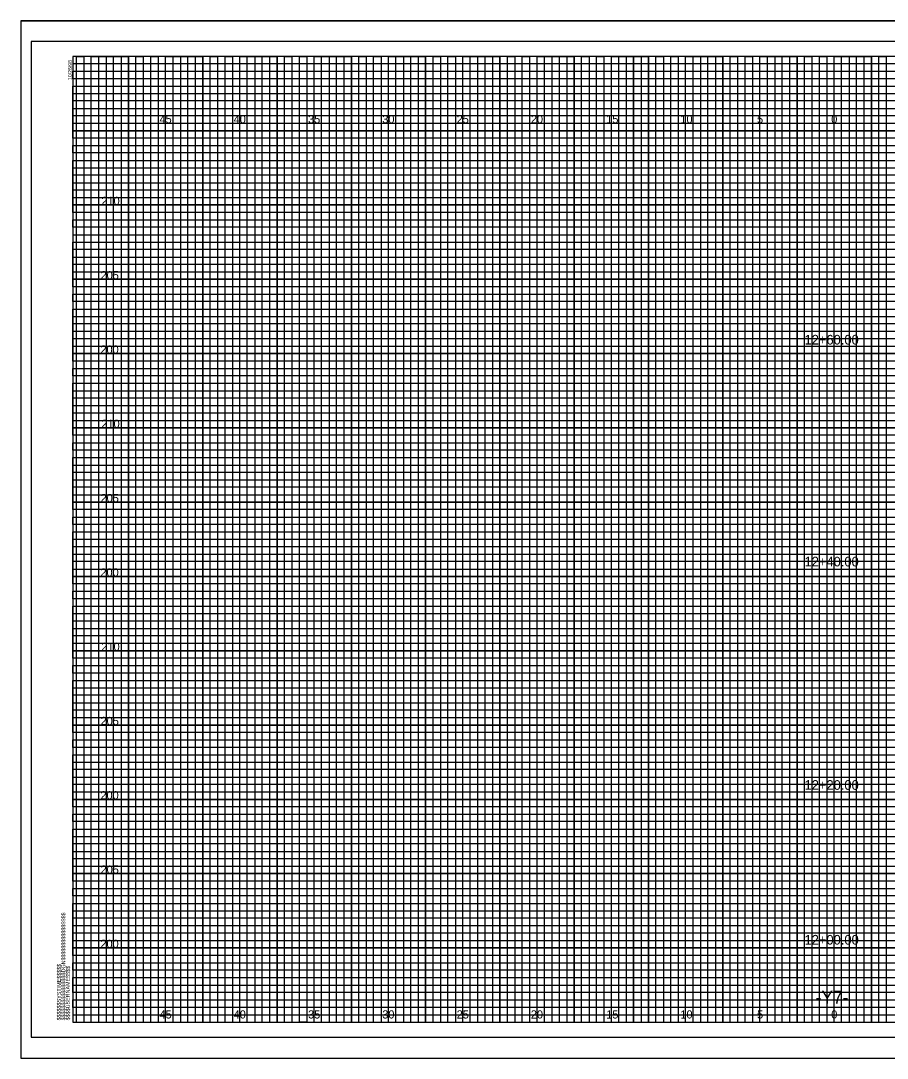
# Model space of a CAD drawing. Extents: x -4 to 103, y -2 to 351.
# Drawn here: x -3.5 to 54.8, y 139.2 to 209.1 of the extents above; entities that cross this region are included whole.
import ezdxf

# ---------------------------------------------------------------- set-up
doc = ezdxf.new("R2010")
doc.units = 0
for name, color, linetype in [('Exist XS Ground Line', 7, 'Continuous'), ('Old_Level_10', 7, 'Continuous'), ('Old_Level_16', 7, 'Continuous'), ('Old_Level_3', 7, 'Continuous'), ('Old_Level_4', 7, 'Continuous'), ('Old_Level_5', 7, 'Continuous'), ('Old_Level_6', 7, 'Continuous'), ('Old_Level_8', 7, 'Continuous'), ('Prop XS Finish Grade', 7, 'Continuous'), ('Prop XS SE Text', 7, 'Continuous'), ('Prop XS Subgrade Earthwork', 7, 'Continuous')]:
    doc.layers.add(name, color=color, linetype=linetype)

msp = doc.modelspace()

# ---------------------------------------------------------------- linework, layer by layer
at = {"layer": 'Old_Level_10'}
for p, q in [((1.25, 141.65), (1.25, 206.65)), ((3.75, 141.65), (3.75, 206.65)), ((6.25, 141.65), (6.25, 206.65)), ((8.75, 141.65), (8.75, 206.65)), ((11.25, 141.65), (11.25, 206.65)), ((13.75, 141.65), (13.75, 206.65)), ((16.25, 141.65), (16.25, 206.65)), ((18.75, 141.65), (18.75, 206.65)), ((21.25, 141.65), (21.25, 206.65)), ((23.75, 141.65), (23.75, 206.65)), ((26.25, 141.65), (26.25, 206.65)), ((28.75, 141.65), (28.75, 206.65)), ((31.25, 141.65), (31.25, 206.65)), ((33.75, 141.65), (33.75, 206.65)), ((36.25, 141.65), (36.25, 206.65)), ((38.75, 141.65), (38.75, 206.65)), ((41.25, 141.65), (41.25, 206.65)), ((43.75, 141.65), (43.75, 206.65)), ((46.25, 141.65), (46.25, 206.65)), ((48.75, 141.65), (48.75, 206.65)), ((51.25, 141.65), (51.25, 206.65)), ((53.75, 141.65), (53.75, 206.65)), ((0, 204.15), (74.25, 204.15)), ((0, 201.65), (102.5, 201.65)), ((0, 199.15), (102.5, 199.15)), ((0, 196.65), (102.5, 196.65)), ((0, 194.15), (102.5, 194.15)), ((0, 191.65), (102.5, 191.65)), ((0, 189.15), (102.5, 189.15)), ((0, 186.65), (102.5, 186.65)), ((0, 184.15), (102.5, 184.15)), ((0, 181.65), (102.5, 181.65)), ((0, 179.15), (102.5, 179.15)), ((0, 176.65), (102.5, 176.65)), ((0, 174.15), (102.5, 174.15)), ((0, 171.65), (102.5, 171.65)), ((0, 169.15), (102.5, 169.15)), ((0, 166.65), (102.5, 166.65)), ((0, 164.15), (102.5, 164.15)), ((0, 161.65), (102.5, 161.65)), ((0, 159.15), (102.5, 159.15)), ((0, 156.65), (102.5, 156.65)), ((0, 154.15), (102.5, 154.15)), ((0, 151.65), (102.5, 151.65)), ((0, 149.15), (102.5, 149.15)), ((0, 146.65), (102.5, 146.65)), ((0, 144.15), (102.5, 144.15))]:
    msp.add_line(p, q, dxfattribs=at)
at = {"layer": 'Old_Level_3'}
for p, q in [((-3.5, 209.05), (103.4, 209.05)), ((-3.5, 209.05), (-3.5, 139.225)), ((-3.5, 139.225), (102.1625, 139.225))]:
    msp.add_line(p, q, dxfattribs=at)
at = {"layer": 'Old_Level_4'}
for points in [[(0, 203.65), (0, 204.65), (74.25, 204.65), (74.25, 205.15), (0, 205.15), (0, 205.65), (74.25, 205.65), (74.25, 206.15), (0, 206.15)], [(0.25, 141.65), (0.25, 206.65), (0.75, 206.65), (0.75, 141.65), (1.75, 141.65), (1.75, 206.65), (2.25, 206.65), (2.25, 141.65), (2.75, 141.65), (2.75, 206.65), (3.25, 206.65), (3.25, 141.65), (4.25, 141.65), (4.25, 206.65), (4.75, 206.65), (4.75, 141.65), (5.25, 141.65), (5.25, 206.65), (5.75, 206.65), (5.75, 141.65), (6.75, 141.65), (6.75, 206.65), (7.25, 206.65), (7.25, 141.65), (7.75, 141.65), (7.75, 206.65), (8.25, 206.65), (8.25, 141.65), (9.25, 141.65), (9.25, 206.65), (9.75, 206.65), (9.75, 141.65), (10.25, 141.65), (10.25, 206.65), (10.75, 206.65), (10.75, 141.65), (11.75, 141.65), (11.75, 206.65), (12.25, 206.65), (12.25, 141.65), (12.75, 141.65), (12.75, 206.65), (13.25, 206.65), (13.25, 141.65), (14.25, 141.65), (14.25, 206.65), (14.75, 206.65), (14.75, 141.65), (15.75, 141.65), (15.25, 141.65), (15.25, 206.65), (15.75, 206.65), (15.75, 141.65), (16.75, 141.65), (16.75, 206.65), (17.25, 206.65), (17.25, 141.65), (17.75, 141.65), (17.75, 206.65), (18.25, 206.65), (18.25, 141.65), (19.25, 141.65), (19.25, 206.65), (19.75, 206.65), (19.75, 141.65), (20.25, 141.65), (20.25, 206.65), (20.75, 206.65), (20.75, 141.65), (21.75, 141.65), (21.75, 206.65), (22.25, 206.65), (22.25, 141.65), (22.75, 141.65), (22.75, 206.65), (23.25, 206.65), (23.25, 141.65), (24.25, 141.65), (24.25, 206.65), (24.75, 206.65), (24.75, 141.65), (25.25, 141.65), (25.25, 206.65), (25.75, 206.65), (25.75, 141.65), (26.75, 141.65), (26.75, 206.65), (27.25, 206.65), (27.25, 141.65), (27.75, 141.65), (27.75, 206.65), (28.25, 206.65), (28.25, 141.65), (29.25, 141.65), (29.25, 206.65), (29.75, 206.65), (29.75, 141.65), (30.25, 141.65), (30.25, 206.65), (30.75, 206.65), (30.75, 141.65)], [(30.75, 141.65), (31.75, 141.65), (31.75, 206.65), (32.25, 206.65), (32.25, 141.65), (32.75, 141.65), (32.75, 206.65), (33.25, 206.65), (33.25, 141.65), (34.25, 141.65), (34.25, 206.65), (34.75, 206.65), (34.75, 141.65), (35.25, 141.65), (35.25, 206.65), (35.75, 206.65), (35.75, 141.65), (36.75, 141.65), (36.75, 206.65), (37.25, 206.65), (37.25, 141.65), (37.75, 141.65), (37.75, 206.65), (37.75, 141.65)], [(38.25, 206.65), (38.25, 141.65), (39.25, 141.65), (39.25, 206.65), (39.75, 206.65), (39.75, 141.65), (40.25, 141.65), (40.25, 206.65), (40.75, 206.65), (40.75, 141.65), (41.75, 141.65), (41.75, 206.65), (42.25, 206.65), (42.25, 141.65), (42.75, 141.65), (42.75, 206.65), (43.25, 206.65), (43.25, 141.65), (43.75, 141.65), (44.25, 141.65), (44.25, 206.65), (44.75, 206.65), (44.75, 141.65), (45.25, 141.65), (45.25, 206.65), (45.75, 206.65), (45.75, 141.65), (46.75, 141.65), (46.75, 206.65), (47.25, 206.65), (47.25, 141.65), (47.75, 141.65), (47.75, 206.65), (48.25, 206.65), (48.25, 141.65), (49.25, 141.65), (49.25, 206.65), (49.75, 206.65), (49.75, 141.65), (50.25, 141.65), (50.25, 206.65), (50.75, 206.65), (50.75, 141.65), (51.75, 141.65), (51.75, 206.65), (52.25, 206.65), (52.25, 141.65), (52.75, 141.65), (52.75, 206.65), (53.25, 206.65), (53.25, 141.65), (54.25, 141.65), (54.25, 206.65), (54.75, 206.65), (54.75, 141.65), (55.25, 141.65)], [(102.5, 203.65), (0, 203.65)], [(102.5, 202.65), (0, 202.65), (0, 203.15), (102.5, 203.15)], [(102.5, 201.15), (0, 201.15), (0, 202.15), (102.5, 202.15)], [(102.5, 200.15), (0, 200.15), (0, 200.65), (102.5, 200.65)], [(102.5, 198.65), (0, 198.65), (0, 199.65), (102.5, 199.65)], [(102.5, 197.65), (0, 197.65), (0, 198.15), (102.5, 198.15)], [(102.5, 196.15), (0, 196.15), (0, 197.15), (102.5, 197.15)], [(102.5, 195.15), (0, 195.15), (0, 195.65), (102.5, 195.65)], [(0, 194.65), (102.5, 194.65)], [(102.5, 193.65), (0, 193.65)], [(102.5, 192.65), (0, 192.65), (0, 193.15), (102.5, 193.15)], [(102.5, 191.15), (0, 191.15), (0, 192.15), (102.5, 192.15)], [(102.5, 190.15), (0, 190.15), (0, 190.65), (102.5, 190.65)], [(102.5, 188.65), (0, 188.65), (0, 189.65), (102.5, 189.65)], [(102.5, 187.65), (0, 187.65), (0, 188.15), (102.5, 188.15)], [(102.5, 186.15), (0, 186.15), (0, 187.15), (102.5, 187.15)], [(102.5, 185.15), (0, 185.15), (0, 185.65), (102.5, 185.65)], [(102.5, 183.65), (0, 183.65), (0, 184.65), (102.5, 184.65)], [(102.5, 182.65), (0, 182.65), (0, 183.15), (102.5, 183.15)], [(102.5, 181.15), (0, 181.15), (0, 182.15), (102.5, 182.15)], [(102.5, 180.15), (0, 180.15), (0, 180.65), (102.5, 180.65)], [(102.5, 178.65), (0, 178.65), (0, 179.65), (102.5, 179.65)], [(102.5, 177.65), (0, 177.65), (0, 178.15), (102.5, 178.15)], [(102.5, 176.15), (0, 176.15), (0, 177.15), (102.5, 177.15)], [(102.5, 175.15), (0, 175.15), (0, 175.65), (102.5, 175.65)], [(102.5, 173.65), (0, 173.65), (0, 174.65), (102.5, 174.65)], [(102.5, 172.65), (0, 172.65), (0, 173.15)], [(0, 173.15), (102.5, 173.15)], [(102.5, 171.15), (0, 171.15), (0, 172.15), (102.5, 172.15)], [(102.5, 170.15), (0, 170.15), (0, 170.65), (102.5, 170.65)], [(102.5, 168.65), (0, 168.65), (0, 169.65), (102.5, 169.65)], [(102.5, 167.65), (0, 167.65), (0, 168.15), (102.5, 168.15)], [(102.5, 166.15), (0, 166.15), (0, 167.15), (102.5, 167.15)], [(102.5, 165.15), (0, 165.15), (0, 165.65), (102.5, 165.65)], [(102.5, 163.65), (0, 163.65), (0, 164.65), (102.5, 164.65)], [(102.5, 162.65), (0, 162.65), (0, 163.15), (102.5, 163.15)], [(102.5, 161.15), (0, 161.15), (0, 162.15), (102.5, 162.15)], [(102.5, 160.15), (0, 160.15), (0, 160.65), (102.5, 160.65)], [(102.5, 158.65), (0, 158.65), (0, 159.65), (102.5, 159.65)], [(102.5, 157.65), (0, 157.65), (0, 158.15), (102.5, 158.15)], [(102.5, 156.15), (0, 156.15), (0, 157.15), (102.5, 157.15)], [(102.5, 155.15), (0, 155.15), (0, 155.65), (102.5, 155.65)], [(102.5, 153.65), (0, 153.65), (0, 154.65), (102.5, 154.65)], [(102.5, 152.65), (0, 152.65), (0, 153.15), (102.5, 153.15)], [(102.5, 151.15), (0, 151.15), (0, 152.15), (102.5, 152.15)], [(102.5, 150.15), (0, 150.15), (0, 150.65), (102.5, 150.65)], [(102.5, 148.65), (0, 148.65), (0, 149.65), (102.5, 149.65)], [(102.5, 147.65), (0, 147.65), (0, 148.15), (102.5, 148.15)], [(102.5, 146.15), (0, 146.15), (0, 147.15), (102.5, 147.15)], [(102.5, 145.15), (0, 145.15), (0, 145.65), (102.5, 145.65)], [(102.5, 143.65), (0, 143.65), (0, 144.65), (102.5, 144.65)], [(102.5, 142.65), (0, 142.65), (0, 143.15), (102.5, 143.15)], [(0, 142.15), (102.5, 142.15)]]:
    msp.add_lwpolyline(points, dxfattribs=at)
at = {"layer": 'Old_Level_5'}
msp.add_lwpolyline([(103.4, 209.05), (-3.5, 209.05), (-3.5, 139.225), (103.4, 139.225)], close=True, dxfattribs=at)
at = {"layer": 'Old_Level_6'}
for p, q in [((0, 141.65), (0, 141.65)), ((0, 141.65), (0, 141.65)), ((-3.5, 139.225), (103.4, 139.225))]:
    msp.add_line(p, q, dxfattribs=at)
msp.add_lwpolyline([(102.5, 206.65), (0, 206.65), (0, 141.65), (102.5, 141.65)], close=True, dxfattribs=at)
at = {"layer": 'Old_Level_8'}
for points in [[(1.25, 141.65), (1.25, 206.65), (3.75, 206.65), (3.75, 141.65), (6.25, 141.65), (6.25, 206.65), (8.75, 206.65), (8.75, 141.65), (11.25, 141.65), (11.25, 206.65), (13.75, 206.65), (13.75, 141.65), (16.25, 141.65), (16.25, 206.65), (18.75, 206.65), (18.75, 141.65), (21.25, 141.65), (21.25, 206.65), (23.75, 206.65), (23.75, 141.65), (26.25, 141.65), (26.25, 206.65), (28.75, 206.65), (28.75, 141.65), (31.25, 141.65), (31.25, 206.65), (33.75, 206.65), (33.75, 141.65), (36.25, 141.65), (36.25, 206.65), (38.75, 206.65), (38.75, 141.65), (41.25, 141.65), (41.25, 206.65), (43.75, 206.65), (43.75, 141.65), (46.25, 141.65), (46.25, 206.65), (48.75, 206.65), (48.75, 141.65), (51.25, 141.65), (51.25, 206.65), (53.75, 206.65), (53.75, 141.65)], [(102.5, 201.65), (0, 201.65), (0, 204.15), (74.25, 204.15)], [(102.5, 196.65), (0, 196.65), (0, 199.15), (102.5, 199.15)], [(102.5, 191.65), (0, 191.65), (0, 194.15), (102.5, 194.15)], [(102.5, 186.65), (0, 186.65), (0, 189.15), (102.5, 189.15)], [(102.5, 181.65), (0, 181.65), (0, 184.15), (102.5, 184.15)], [(102.5, 176.65), (0, 176.65), (0, 179.15), (102.5, 179.15)], [(102.5, 171.65), (0, 171.65), (0, 174.15), (102.5, 174.15)], [(102.5, 166.65), (0, 166.65), (0, 169.15), (102.5, 169.15)], [(102.5, 161.65), (0, 161.65), (0, 164.15), (102.5, 164.15)], [(102.5, 156.65), (0, 156.65), (0, 159.15), (102.5, 159.15)], [(102.5, 151.65), (0, 151.65), (0, 154.15), (102.5, 154.15)], [(102.5, 146.65), (0, 146.65), (0, 149.15), (102.5, 149.15)], [(0, 144.15), (102.5, 144.15)]]:
    msp.add_lwpolyline(points, dxfattribs=at)
at = {"layer": 'Prop XS SE Text'}
msp.add_lwpolyline([(103, 207.65), (-2.8, 207.65), (-2.8, 140.65), (103, 140.65)], close=True, dxfattribs=at)

# ---------------------------------------------------------------- texts
at = {"layer": 'Exist XS Ground Line'}
msp.add_text('-Y7-', height=0.875, dxfattribs=at).set_placement((49.9985, 142.9))
at = {"layer": 'Old_Level_16'}
for s, p in [('45', (5.8399, 202.15)), ('40', (10.8313, 202.15)), ('35', (15.8399, 202.15)), ('30', (20.8313, 202.15)), ('25', (25.8399, 202.15)), ('20', (30.8313, 202.15)), ('15', (35.9058, 202.15)), ('10', (40.8971, 202.15)), ('5', (46.0574, 202.15)), ('0', (51.0488, 202.15)), ('0', (51.0488, 202.15)), ('45', (5.8399, 141.9)), ('40', (10.8313, 141.9)), ('35', (15.8399, 141.9)), ('30', (20.8313, 141.9)), ('25', (25.8399, 141.9)), ('20', (30.8313, 141.9)), ('15', (35.9058, 141.9)), ('10', (40.8971, 141.9)), ('5', (46.0574, 141.9)), ('0', (51.0488, 141.9)), ('0', (51.0488, 141.9))]:
    msp.add_text(s, height=0.55, dxfattribs=at).set_placement(p)
at = {"layer": 'Old_Level_6'}
for s, height, p in [('10/26/98', 0.25, (-0.0625, 205.0595)), ('$$$$$$$$$$$$$$$$DGN$$$$$$$$$$$$$$$$', 0.2625, (-0.5, 141.775)), ('$$$$$$SYSTIME$$$$$', 0.2625, (-0.7973, 141.7747)), ('$$$$USERNAME$$$$', 0.2625, (-0.2, 141.775))]:
    msp.add_text(s, height=height, rotation=90, dxfattribs=at).set_placement(p)
at = {"layer": 'Old_Level_8'}
msp.add_text('040397', height=0.0025, rotation=90, dxfattribs=at).set_placement((-0.0007, 206.6364))
at = {"layer": 'Prop XS Finish Grade'}
for s, p in [('210', (1.9296, 196.65)), ('205', (1.8724, 191.65)), ('200', (1.8638, 186.65)), ('210', (1.9296, 181.65)), ('205', (1.8724, 176.65)), ('200', (1.8638, 171.65)), ('210', (1.9296, 166.65)), ('205', (1.8724, 161.65)), ('200', (1.8638, 156.65)), ('205', (1.8724, 151.65)), ('200', (1.8638, 146.65))]:
    msp.add_text(s, height=0.55, dxfattribs=at).set_placement(p)
at = {"layer": 'Prop XS Subgrade Earthwork'}
for s, p in [('12+60.00', (49.2508, 187.2589)), ('12+40.00', (49.2508, 172.3254)), ('12+20.00', (49.2508, 157.2908)), ('12+00.00', (49.2508, 146.8744))]:
    msp.add_text(s, height=0.65, dxfattribs=at).set_placement(p)

doc.saveas('drawing.dxf')
